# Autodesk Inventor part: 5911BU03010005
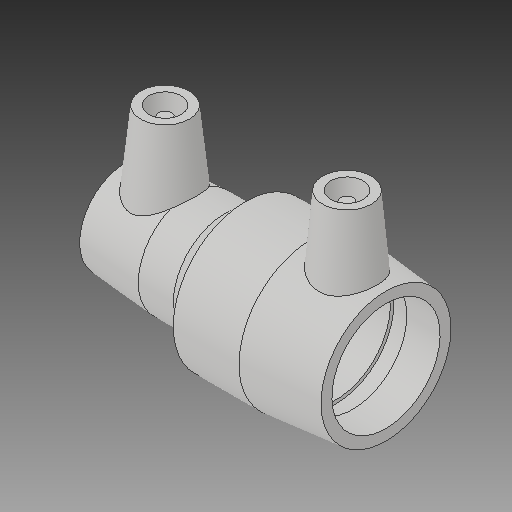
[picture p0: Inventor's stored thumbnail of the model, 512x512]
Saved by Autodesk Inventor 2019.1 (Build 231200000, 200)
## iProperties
Created: 2017-06
Part Number: 5911BU03010005
Material: Generic
Description: PLASSON ASTM REDUCING COUPLER 1''IPS-1/2''CTS
Document SubType Name: Modeling
Designer: KIM
Mass: 54.8237 g
Surface Area: 155.252 cm^2
Volume: 54.8237 cm^3
Density: 1 g/cm^3
Appearance: Default
Author: KIM
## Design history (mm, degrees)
derived "5911.ipt"
feature "Solid1::5911.ipt"
tag "TaggingFeature1"
body "Solid1"
other parameters: "d0" = 80.01, "d2" = 31.75, "d3" = 32.766, "d4" = 19.6596, "d5" = 28.575, "d7" = 15.8, "d8" = 168 deg, "d10" = 13.1064, "d11" = 4.3688, "d14" = 17.6296, "d22" = 108.92847, "d29" = 35.56, "d30" = 15, "d31" = 28.0035, "d34" = 6 deg, "d41" = 4, "d42" = 14, "d43" = 0, "d48" = 31.75, "d49" = 33.3, "d50" = 44.45, "d52" = 14.22, "d53" = 15.3416, "d54" = 5.11387, "d55" = 168 deg, "d56" = 23.0124, "d57" = 38.354, "d58" = 40.005, "d59" = 1.6383, "d60" = 135 deg, "d61" = 40.894, "d62" = 15, "d64" = 4, "d66" = 5 deg, "d67" = 14, "d68" = 0, "d69" = 28.0035, "d95" = 3, "d96" = 0, "d97" = 3, "d98" = 0, "d_1" = 15.8, "L_" = 80.01, "L_2" = 32.766, "D_1" = 31.75, "A_1" = 35.56, "d_2" = 12, "L_1" = 38.354, "d_" = 33.3, "A_" = 40.894, "D_" = 44.45
